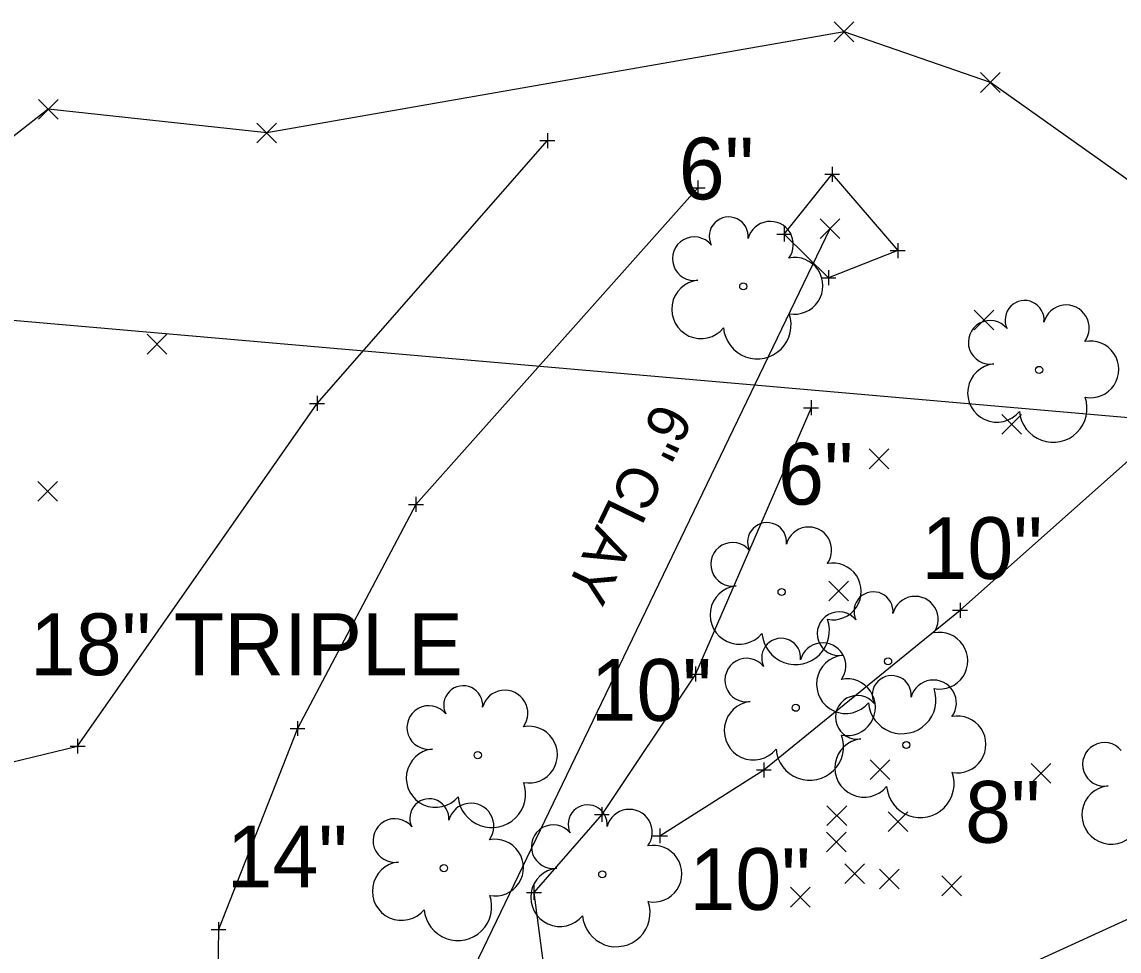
# Model space of a CAD drawing. Extents: x 2005176 to 2005823, y 572472 to 572942.
# Drawn here: x 2005497.2 to 2005571.3, y 572648.8 to 572711.5 of the extents above; entities that cross this region are included whole.
import ezdxf

# ---------------------------------------------------------------- set-up
doc = ezdxf.new("R2010")
doc.units = 0
for name, color, linetype in [('DR_X_Storm_Sewer', 7, 'Continuous'), ('DR_X_Text', 7, 'Continuous'), ('GE_X_Alignment_1000_Cardinal_Points', 7, 'Continuous'), ('GE_X_Alignment_500_Bearings', 7, 'Continuous'), ('GE_X_Alignment_500_Cardinal_Points', 7, 'Continuous'), ('SV_P_Mon_Cells_Set', 7, 'Continuous'), ('SV_X_Random_Point', 7, 'Continuous'), ('SV_X_Shot_Marker', 7, 'Continuous'), ('SV_X_Terrain_Boundary', 7, 'Continuous'), ('UT_X_Overhead_Electric', 7, 'Continuous'), ('VG_X_Text', 7, 'Continuous')]:
    doc.layers.add(name, color=color, linetype=linetype)

msp = doc.modelspace()

# ---------------------------------------------------------------- linework, layer by layer
at = {"layer": 'DR_X_Storm_Sewer'}
msp.add_line((2005525.415, 572642.862), (2005551.774, 572697.546), dxfattribs=at)
at = {"layer": 'GE_X_Alignment_1000_Cardinal_Points'}
msp.add_lwpolyline([(2005589.359, 572669.576), (2005577.827, 572653.684), (2005542.162, 572637.376), (2005475.268, 572632.406), (2005412.503, 572639.628), (2005455.372, 572649.173), (2005453.824, 572664.208)], dxfattribs=at)
at = {"layer": 'GE_X_Alignment_500_Bearings'}
msp.add_lwpolyline([(2005556.337, 572696.065), (2005551.67, 572694.238), (2005548.674, 572697.169), (2005551.912, 572701.216)], close=True, dxfattribs=at)
for points in [[(2005542.844, 572700.296), (2005523.816, 572678.945), (2005515.819, 572663.819), (2005510.488, 572650.261), (2005510.359, 572641.52), (2005504.712, 572639.398), (2005492.739, 572631.706)], [(2005550.488, 572685.468), (2005542.688, 572667.5), (2005536.366, 572658.022), (2005531.779, 572652.766), (2005532.621, 572646.264)], [(2005540.285, 572656.579), (2005547.294, 572661.027), (2005560.544, 572671.799), (2005571.909, 572681.905)]]:
    msp.add_lwpolyline(points, dxfattribs=at)
at = {"layer": 'GE_X_Alignment_500_Cardinal_Points'}
msp.add_lwpolyline([(2005223.697, 572649.478), (2005272.158, 572646.313), (2005321.288, 572642.614), (2005368.446, 572643.698), (2005424.937, 572638.397), (2005464.256, 572637.835), (2005477.307, 572636.749), (2005486.328, 572634.292), (2005489.17, 572649.331), (2005492.031, 572660.48), (2005500.977, 572662.633), (2005517.139, 572685.76), (2005532.685, 572703.484)], dxfattribs=at)
at = {"layer": 'SV_P_Mon_Cells_Set'}
for p, q in [((2005532.685, 572703.984), (2005532.685, 572702.984)), ((2005532.185, 572703.484), (2005533.185, 572703.484)), ((2005532.685, 572703.484), (2005532.685, 572703.484)), ((2005551.912, 572701.716), (2005551.912, 572700.716)), ((2005542.844, 572700.796), (2005542.844, 572699.796)), ((2005551.412, 572701.216), (2005552.412, 572701.216)), ((2005551.912, 572701.216), (2005551.912, 572701.216)), ((2005542.344, 572700.296), (2005543.344, 572700.296)), ((2005542.844, 572700.296), (2005542.844, 572700.296)), ((2005548.174, 572697.169), (2005549.174, 572697.169)), ((2005548.674, 572697.669), (2005548.674, 572696.669)), ((2005548.674, 572697.169), (2005548.674, 572697.169)), ((2005556.337, 572696.565), (2005556.337, 572695.565)), ((2005555.837, 572696.065), (2005556.837, 572696.065)), ((2005556.337, 572696.065), (2005556.337, 572696.065)), ((2005551.67, 572694.738), (2005551.67, 572693.738)), ((2005551.17, 572694.238), (2005552.17, 572694.238)), ((2005551.67, 572694.238), (2005551.67, 572694.238)), ((2005517.139, 572686.26), (2005517.139, 572685.26)), ((2005550.488, 572685.968), (2005550.488, 572684.968)), ((2005516.639, 572685.76), (2005517.639, 572685.76)), ((2005517.139, 572685.76), (2005517.139, 572685.76)), ((2005549.988, 572685.468), (2005550.988, 572685.468)), ((2005550.488, 572685.468), (2005550.488, 572685.468)), ((2005523.816, 572679.445), (2005523.816, 572678.445)), ((2005523.316, 572678.945), (2005524.316, 572678.945)), ((2005523.816, 572678.945), (2005523.816, 572678.945)), ((2005560.044, 572671.799), (2005561.044, 572671.799)), ((2005560.544, 572672.299), (2005560.544, 572671.299)), ((2005560.544, 572671.799), (2005560.544, 572671.799)), ((2005542.188, 572667.5), (2005543.188, 572667.5)), ((2005542.688, 572668), (2005542.688, 572667)), ((2005542.688, 572667.5), (2005542.688, 572667.5)), ((2005515.319, 572663.819), (2005516.319, 572663.819)), ((2005515.819, 572664.319), (2005515.819, 572663.319)), ((2005515.819, 572663.819), (2005515.819, 572663.819)), ((2005500.977, 572663.133), (2005500.977, 572662.133)), ((2005500.477, 572662.633), (2005501.477, 572662.633)), ((2005500.977, 572662.633), (2005500.977, 572662.633)), ((2005547.294, 572661.527), (2005547.294, 572660.527)), ((2005546.794, 572661.027), (2005547.794, 572661.027)), ((2005547.294, 572661.027), (2005547.294, 572661.027)), ((2005536.366, 572658.522), (2005536.366, 572657.522)), ((2005535.866, 572658.022), (2005536.866, 572658.022)), ((2005536.366, 572658.022), (2005536.366, 572658.022)), ((2005540.285, 572657.079), (2005540.285, 572656.079)), ((2005539.785, 572656.579), (2005540.785, 572656.579)), ((2005540.285, 572656.579), (2005540.285, 572656.579)), ((2005531.779, 572653.266), (2005531.779, 572652.266)), ((2005531.279, 572652.766), (2005532.279, 572652.766)), ((2005531.779, 572652.766), (2005531.779, 572652.766)), ((2005510.488, 572650.761), (2005510.488, 572649.761)), ((2005509.988, 572650.261), (2005510.988, 572650.261)), ((2005510.488, 572650.261), (2005510.488, 572650.261))]:
    msp.add_line(p, q, dxfattribs=at)
at = {"layer": 'SV_X_Random_Point'}
for p, q in [((2005552.053, 572710.156), (2005553.386, 572711.491)), ((2005552.053, 572711.491), (2005553.386, 572710.156)), ((2005561.925, 572706.74), (2005563.258, 572708.075)), ((2005561.925, 572708.075), (2005563.258, 572706.74)), ((2005498.325, 572704.934), (2005499.658, 572706.269)), ((2005498.325, 572706.269), (2005499.658, 572704.934)), ((2005513.078, 572703.336), (2005514.411, 572704.671)), ((2005513.078, 572704.671), (2005514.411, 572703.336)), ((2005551.108, 572696.878), (2005552.441, 572698.213)), ((2005551.108, 572698.213), (2005552.441, 572696.878)), ((2005561.491, 572690.719), (2005562.824, 572692.054)), ((2005561.491, 572692.054), (2005562.824, 572690.719)), ((2005505.671, 572689.088), (2005507.005, 572690.423)), ((2005505.671, 572690.423), (2005507.005, 572689.088)), ((2005563.358, 572683.674), (2005564.691, 572685.009)), ((2005563.358, 572685.009), (2005564.691, 572683.674)), ((2005554.413, 572681.347), (2005555.747, 572682.682)), ((2005554.413, 572682.682), (2005555.747, 572681.347)), ((2005498.293, 572679.152), (2005499.627, 572680.487)), ((2005498.293, 572680.487), (2005499.627, 572679.152)), ((2005551.68, 572672.437), (2005553.014, 572673.772)), ((2005551.68, 572673.772), (2005553.014, 572672.437)), ((2005554.477, 572660.373), (2005555.81, 572661.708)), ((2005554.477, 572661.708), (2005555.81, 572660.373)), ((2005565.342, 572660.125), (2005566.676, 572661.46)), ((2005565.342, 572661.46), (2005566.676, 572660.125)), ((2005551.558, 572657.27), (2005552.892, 572658.605)), ((2005551.558, 572658.605), (2005552.892, 572657.27)), ((2005555.694, 572656.865), (2005557.027, 572658.2)), ((2005555.694, 572658.2), (2005557.027, 572656.865)), ((2005551.519, 572655.492), (2005552.852, 572656.827)), ((2005551.519, 572656.827), (2005552.852, 572655.492)), ((2005552.767, 572653.366), (2005554.1, 572654.701)), ((2005552.767, 572654.701), (2005554.1, 572653.366)), ((2005555.097, 572653.007), (2005556.43, 572654.342)), ((2005555.097, 572654.342), (2005556.43, 572653.007)), ((2005559.316, 572652.54), (2005560.649, 572653.875)), ((2005559.316, 572653.875), (2005560.649, 572652.54)), ((2005549.097, 572651.778), (2005550.43, 572653.113)), ((2005549.097, 572653.113), (2005550.43, 572651.778))]:
    msp.add_line(p, q, dxfattribs=at)
at = {"layer": 'SV_X_Shot_Marker'}
for centre in [(2005545.91, 572693.653), (2005565.885, 572688.015), (2005548.498, 572673.034), (2005555.687, 572668.358), (2005549.454, 572665.224), (2005556.918, 572662.711), (2005527.989, 572662.025), (2005525.698, 572654.401), (2005536.39, 572653.988)]:
    msp.add_circle(centre, 0.24, dxfattribs=at)
for centre, radius, start, end in [((2005544.926, 572697.02), 1.317, 354.0047, 205.97412), ((2005547.736, 572696.482), 1.553, 323.82996, 165.0376), ((2005542.601, 572695.517), 1.471, 39.06254, 279.54124), ((2005549.37, 572693.689), 1.915, 259.14531, 101.45961), ((2005543.057, 572692.104), 1.974, 96.17219, 320.57371), ((2005564.902, 572691.383), 1.317, 354.0047, 205.97412), ((2005546.856, 572691.048), 2.284, 184.94757, 19.45715), ((2005567.712, 572690.844), 1.553, 323.82996, 165.0376), ((2005562.576, 572689.879), 1.471, 39.06254, 279.54124), ((2005569.346, 572688.051), 1.915, 259.14531, 101.45961), ((2005563.032, 572686.467), 1.974, 96.17219, 320.57371), ((2005566.832, 572685.41), 2.284, 184.94757, 19.45715), ((2005547.515, 572676.401), 1.317, 354.0047, 205.97412), ((2005550.324, 572675.863), 1.553, 323.82996, 165.0376), ((2005545.189, 572674.898), 1.471, 39.06254, 279.54124), ((2005551.959, 572673.07), 1.915, 259.14531, 101.45961), ((2005545.645, 572671.485), 1.974, 96.17219, 320.57371), ((2005554.704, 572671.726), 1.317, 354.0047, 205.97412), ((2005557.514, 572671.187), 1.553, 323.82996, 165.0376), ((2005549.445, 572670.429), 2.284, 184.94757, 19.45715), ((2005552.378, 572670.222), 1.471, 39.06254, 279.54124), ((2005559.148, 572668.394), 1.915, 259.14531, 101.45961), ((2005548.47, 572668.591), 1.317, 354.0047, 205.97412), ((2005551.28, 572668.053), 1.553, 323.82996, 165.0376), ((2005546.144, 572667.088), 1.471, 39.06254, 279.54124), ((2005552.834, 572666.81), 1.974, 96.17219, 320.57371), ((2005555.934, 572666.079), 1.317, 354.0047, 205.97412), ((2005527.005, 572665.392), 1.317, 354.0047, 205.97412), ((2005552.914, 572665.26), 1.915, 259.14531, 101.45961), ((2005558.744, 572665.541), 1.553, 323.82996, 165.0376), ((2005529.815, 572664.854), 1.553, 323.82996, 165.0376), ((2005553.609, 572664.576), 1.471, 39.06254, 279.54124), ((2005556.634, 572665.753), 2.284, 184.94757, 19.45715), ((2005524.679, 572663.889), 1.471, 39.06254, 279.54124), ((2005546.6, 572663.675), 1.974, 96.17219, 320.57371), ((2005560.378, 572662.747), 1.915, 259.14531, 101.45961), ((2005531.449, 572662.061), 1.915, 259.14531, 101.45961), ((2005550.4, 572662.618), 2.284, 184.94757, 19.45715), ((2005554.065, 572661.163), 1.974, 96.17219, 320.57371), ((2005525.135, 572660.476), 1.974, 96.17219, 320.57371), ((2005570.29, 572661.403), 1.471, 39.06254, 279.54124), ((2005557.865, 572660.106), 2.284, 184.94757, 19.45715), ((2005528.935, 572659.419), 2.284, 184.94757, 19.45715), ((2005570.746, 572657.99), 1.974, 96.17219, 320.57371), ((2005524.715, 572657.769), 1.317, 354.0047, 205.97412), ((2005527.525, 572657.23), 1.553, 323.82996, 165.0376), ((2005535.406, 572657.356), 1.317, 354.0047, 205.97412), ((2005522.389, 572656.265), 1.471, 39.06254, 279.54124), ((2005538.216, 572656.817), 1.553, 323.82996, 165.0376), ((2005533.08, 572655.852), 1.471, 39.06254, 279.54124), ((2005529.159, 572654.437), 1.915, 259.14531, 101.45961), ((2005539.85, 572654.024), 1.915, 259.14531, 101.45961), ((2005522.845, 572652.852), 1.974, 96.17219, 320.57371), ((2005533.536, 572652.44), 1.974, 96.17219, 320.57371), ((2005526.645, 572651.796), 2.284, 184.94757, 19.45715), ((2005537.336, 572651.383), 2.284, 184.94757, 19.45715)]:
    msp.add_arc(centre, radius, start, end, dxfattribs=at)
at = {"layer": 'SV_X_Terrain_Boundary'}
msp.add_lwpolyline([(2005682.423, 572646.035), (2005631.483, 572658.576), (2005562.591, 572707.407), (2005552.719, 572710.824), (2005513.745, 572704.003), (2005498.992, 572705.601), (2005481.51, 572691.942), (2005424.053, 572668.063)], dxfattribs=at)
at = {"layer": 'UT_X_Overhead_Electric'}
msp.add_line((2005462.761, 572694.312), (2005730.632, 572670.977), dxfattribs=at)

# ---------------------------------------------------------------- texts
at = {"layer": 'DR_X_Text'}
msp.add_text('6" CLAY', height=2.8, rotation=244.26427, dxfattribs=at).set_placement((2005540.047, 572685.96))
at = {"layer": 'VG_X_Text'}
for s, p in [('6"', (2005541.558, 572699.521)), ('6"', (2005548.264, 572678.928)), ('10"', (2005557.943, 572673.911)), ('10"', (2005557.943, 572673.911)), ('18" TRIPLE', (2005497.755, 572667.421)), ('10"', (2005535.606, 572664.344)), ('8"', (2005560.885, 572656.115)), ('14"', (2005511.03, 572653.105)), ('10"', (2005542.277, 572651.583))]:
    msp.add_text(s, height=4.1667, dxfattribs=at).set_placement(p)

doc.saveas('drawing.dxf')
